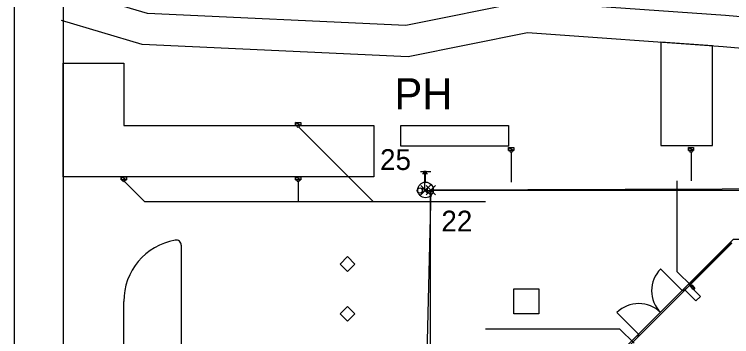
# Model space of a CAD drawing. Extents: x -263964 to -263544, y -1242317 to -1242020.
# Drawn here: x -263964.1 to -263895.1, y -1242096.7 to -1242065.7 of the extents above; entities that cross this region are included whole.
import ezdxf

# ---------------------------------------------------------------- set-up
doc = ezdxf.new("R2010")
doc.units = 0
for name, color, linetype in [('KFA_KOORDINACNA_SITUACIA_DSP_SEDA', 7, 'Continuous'), ('KFA_SO_50-2_POZIARNY_VODOVOD_BODY', 7, 'Continuous'), ('KFA_SO_50-2_POZIARNY_VODOVOD_NADZEMNE_PRVKY', 7, 'Continuous'), ('KFA_SO_50-2_POZIARNY_VODOVOD_TRASA', 7, 'Continuous'), ('POPIS', 7, 'Continuous'), ('RAM_NA_TLAC_A3_1-100', 7, 'Continuous')]:
    doc.layers.add(name, color=color, linetype=linetype)

msp = doc.modelspace()

# ---------------------------------------------------------------- linework, layer by layer
at = {"layer": 'KFA_KOORDINACNA_SITUACIA_DSP_SEDA'}
for p, q in [((-263959.468, -1242059.534), (-263959.468, -1242179.482)), ((-263896.968, -1242068.731), (-263901.968, -1242068.376)), ((-263901.968, -1242068.376), (-263901.968, -1242074.382)), ((-263896.968, -1242074.382), (-263896.968, -1242068.731)), ((-263959.468, -1242071.382), (-263959.468, -1242070.382)), ((-263959.468, -1242070.382), (-263953.617, -1242070.382)), ((-263953.617, -1242070.382), (-263953.617, -1242076.382)), ((-263959.468, -1242076.382), (-263959.468, -1242071.382)), ((-263901.968, -1242074.382), (-263901.968, -1242078.308)), ((-263896.968, -1242078.308), (-263896.968, -1242074.382)), ((-263959.468, -1242081.307), (-263959.468, -1242076.382)), ((-263953.617, -1242076.382), (-263929.58, -1242076.382)), ((-263937.093, -1242076.382), (-263937.093, -1242076.092)), ((-263937.093, -1242076.092), (-263936.593, -1242076.092)), ((-263936.593, -1242076.382), (-263937.093, -1242076.092)), ((-263936.593, -1242076.382), (-263937.093, -1242076.092)), ((-263937.093, -1242076.092), (-263937.093, -1242076.382)), ((-263936.593, -1242076.382), (-263937.093, -1242076.382)), ((-263937.093, -1242076.382), (-263936.593, -1242076.382)), ((-263936.772, -1242076.553), (-263929.628, -1242083.697)), ((-263936.593, -1242076.092), (-263936.593, -1242076.382)), ((-263929.58, -1242076.382), (-263929.58, -1242081.307)), ((-263926.968, -1242076.382), (-263921.968, -1242076.382)), ((-263926.968, -1242078.382), (-263926.968, -1242076.382)), ((-263926.968, -1242076.382), (-263926.968, -1242076.382)), ((-263921.968, -1242076.382), (-263916.593, -1242076.382)), ((-263916.593, -1242076.382), (-263916.593, -1242078.382)), ((-263921.968, -1242078.382), (-263926.968, -1242078.382)), ((-263916.593, -1242078.382), (-263921.968, -1242078.382)), ((-263916.593, -1242078.777), (-263916.593, -1242078.487)), ((-263916.593, -1242078.487), (-263916.093, -1242078.487)), ((-263916.093, -1242078.777), (-263916.593, -1242078.487)), ((-263916.093, -1242078.777), (-263916.593, -1242078.487)), ((-263916.593, -1242078.487), (-263916.593, -1242078.777)), ((-263916.093, -1242078.487), (-263916.093, -1242078.777)), ((-263901.968, -1242078.308), (-263896.968, -1242078.308)), ((-263899.296, -1242078.777), (-263899.296, -1242078.487)), ((-263899.296, -1242078.487), (-263898.796, -1242078.487)), ((-263898.796, -1242078.777), (-263899.296, -1242078.487)), ((-263898.796, -1242078.777), (-263899.296, -1242078.487)), ((-263899.296, -1242078.487), (-263899.296, -1242078.777)), ((-263898.796, -1242078.487), (-263898.796, -1242078.777)), ((-263916.093, -1242078.777), (-263916.593, -1242078.777)), ((-263916.593, -1242078.777), (-263916.093, -1242078.777)), ((-263916.343, -1242078.977), (-263916.343, -1242081.82)), ((-263898.796, -1242078.777), (-263899.296, -1242078.777)), ((-263899.296, -1242078.777), (-263898.796, -1242078.777)), ((-263899.046, -1242078.977), (-263899.047, -1242081.696)), ((-263924.768, -1242081.015), (-263924.768, -1242080.765)), ((-263924.768, -1242080.765), (-263924.518, -1242080.765)), ((-263924.518, -1242080.765), (-263924.518, -1242081.015)), ((-263953.617, -1242081.307), (-263959.468, -1242081.307)), ((-263953.868, -1242081.597), (-263953.868, -1242081.307)), ((-263953.868, -1242081.307), (-263953.368, -1242081.307)), ((-263953.368, -1242081.597), (-263953.868, -1242081.307)), ((-263953.368, -1242081.597), (-263953.868, -1242081.307)), ((-263953.868, -1242081.307), (-263953.868, -1242081.597)), ((-263929.58, -1242081.307), (-263953.617, -1242081.307)), ((-263953.368, -1242081.307), (-263953.368, -1242081.597)), ((-263937.093, -1242081.597), (-263937.093, -1242081.307)), ((-263937.093, -1242081.307), (-263936.593, -1242081.307)), ((-263936.593, -1242081.597), (-263937.093, -1242081.307)), ((-263936.593, -1242081.597), (-263937.093, -1242081.307)), ((-263937.093, -1242081.307), (-263937.093, -1242081.597)), ((-263936.593, -1242081.307), (-263936.593, -1242081.597)), ((-263924.893, -1242081.015), (-263924.768, -1242081.015)), ((-263924.643, -1242082.64), (-263924.643, -1242080.89)), ((-263924.518, -1242081.015), (-263924.393, -1242081.015)), ((-263953.368, -1242081.597), (-263953.868, -1242081.597)), ((-263953.868, -1242081.597), (-263953.368, -1242081.597)), ((-263953.618, -1242081.697), (-263951.618, -1242083.697)), ((-263953.547, -1242081.768), (-263951.618, -1242083.697)), ((-263936.593, -1242081.597), (-263937.093, -1242081.597)), ((-263937.093, -1242081.597), (-263936.593, -1242081.597)), ((-263936.843, -1242081.797), (-263936.843, -1242083.697)), ((-263900.379, -1242090.456), (-263900.379, -1242081.705)), ((-263924.393, -1242082.39), (-263924.893, -1242082.89)), ((-263924.893, -1242082.89), (-263924.893, -1242082.39)), ((-263924.893, -1242082.39), (-263924.393, -1242082.89)), ((-263924.393, -1242082.89), (-263924.393, -1242082.39)), ((-263924.393, -1242082.64), (-263924.143, -1242082.64)), ((-263788.143, -1242082.64), (-263924.143, -1242082.64)), ((-263924.143, -1242082.64), (-263924.143, -1242185.14)), ((-263951.618, -1242083.697), (-263918.806, -1242083.697)), ((-263908.663, -1242101.215), (-263895.135, -1242087.687)), ((-263895.258, -1242087.647), (-263896.566, -1242088.955)), ((-263896.548, -1242088.973), (-263895.24, -1242087.665)), ((-263895.273, -1242087.698), (-263895.245, -1242087.67)), ((-263895.202, -1242087.769), (-263895.273, -1242087.698)), ((-263895.24, -1242087.665), (-263895.258, -1242087.647)), ((-263895.245, -1242087.67), (-263895.216, -1242087.641)), ((-263895.216, -1242087.641), (-263895.146, -1242087.712)), ((-263895.146, -1242087.712), (-263895.202, -1242087.769)), ((-263948.093, -1242087.901), (-263948.093, -1242241.458)), ((-263932.8, -1242089.707), (-263932.093, -1242089)), ((-263932.093, -1242089), (-263931.386, -1242089.707)), ((-263932.093, -1242089), (-263932.093, -1242089)), ((-263897.906, -1242090.295), (-263896.598, -1242088.987)), ((-263896.58, -1242089.005), (-263897.888, -1242090.313)), ((-263896.598, -1242088.987), (-263896.58, -1242089.005)), ((-263896.592, -1242089.017), (-263896.564, -1242088.989)), ((-263896.522, -1242089.088), (-263896.592, -1242089.017)), ((-263896.566, -1242088.955), (-263896.548, -1242088.973)), ((-263896.564, -1242088.989), (-263896.536, -1242088.96)), ((-263896.536, -1242088.96), (-263896.465, -1242089.031)), ((-263896.465, -1242089.031), (-263896.522, -1242089.088)), ((-263932.093, -1242090.414), (-263932.8, -1242089.707)), ((-263931.386, -1242089.707), (-263932.093, -1242090.414)), ((-263899.866, -1242092.276), (-263901.97, -1242090.173)), ((-263899.018, -1242091.817), (-263900.379, -1242090.456)), ((-263899.25, -1242091.639), (-263897.942, -1242090.331)), ((-263897.924, -1242090.349), (-263899.232, -1242091.657)), ((-263897.942, -1242090.331), (-263897.924, -1242090.349)), ((-263897.936, -1242090.361), (-263897.908, -1242090.333)), ((-263897.865, -1242090.432), (-263897.936, -1242090.361)), ((-263897.908, -1242090.333), (-263897.88, -1242090.304)), ((-263897.888, -1242090.313), (-263897.906, -1242090.295)), ((-263897.88, -1242090.304), (-263897.809, -1242090.375)), ((-263897.809, -1242090.375), (-263897.865, -1242090.432)), ((-263899.207, -1242091.764), (-263899.631, -1242092.188)), ((-263899.255, -1242091.68), (-263899.227, -1242091.652)), ((-263899.185, -1242091.751), (-263899.255, -1242091.68)), ((-263899.232, -1242091.657), (-263899.25, -1242091.639)), ((-263899.227, -1242091.652), (-263899.199, -1242091.624)), ((-263898.147, -1242092.824), (-263899.207, -1242091.764)), ((-263899.199, -1242091.624), (-263899.128, -1242091.694)), ((-263899.128, -1242091.694), (-263899.185, -1242091.751)), ((-263898.804, -1242091.866), (-263898.882, -1242091.787)), ((-263916.093, -1242092.107), (-263913.693, -1242092.107)), ((-263916.093, -1242094.507), (-263916.093, -1242092.107)), ((-263913.693, -1242092.107), (-263913.693, -1242094.507)), ((-263899.849, -1242092.259), (-263899.866, -1242092.276)), ((-263899.764, -1242092.174), (-263899.849, -1242092.259)), ((-263899.849, -1242092.259), (-263899.764, -1242092.344)), ((-263899.679, -1242092.259), (-263899.764, -1242092.174)), ((-263899.764, -1242092.344), (-263899.679, -1242092.259)), ((-263899.631, -1242092.188), (-263898.571, -1242093.249)), ((-263898.969, -1242092.031), (-263899.047, -1242091.953)), ((-263899.047, -1242091.953), (-263898.969, -1242092.031)), ((-263898.949, -1242092.031), (-263898.969, -1242092.031)), ((-263898.861, -1242092.119), (-263898.949, -1242092.031)), ((-263898.804, -1242091.885), (-263898.804, -1242091.866)), ((-263898.715, -1242091.974), (-263898.804, -1242091.885)), ((-263898.571, -1242093.249), (-263898.147, -1242092.824)), ((-263953.617, -1242244.458), (-263953.617, -1242093.307)), ((-263932.8, -1242094.507), (-263932.093, -1242093.8)), ((-263932.093, -1242093.8), (-263931.386, -1242094.507)), ((-263932.093, -1242093.8), (-263932.093, -1242093.8)), ((-263932.093, -1242095.214), (-263932.8, -1242094.507)), ((-263931.386, -1242094.507), (-263932.093, -1242095.214)), ((-263913.693, -1242094.507), (-263916.093, -1242094.507)), ((-263904.074, -1242096.484), (-263906.177, -1242094.38)), ((-263905.894, -1242095.971), (-263918.832, -1242095.971)), ((-263904.533, -1242097.332), (-263905.894, -1242095.971)), ((-263904.176, -1242096.586), (-263904.091, -1242096.501)), ((-263904.091, -1242096.671), (-263904.176, -1242096.586)), ((-263904.091, -1242096.501), (-263904.074, -1242096.484)), ((-263904.091, -1242096.501), (-263904.006, -1242096.586)), ((-263904.006, -1242096.586), (-263904.091, -1242096.671))]:
    msp.add_line(p, q, dxfattribs=at)
for points in [[(-263864.257, -1242068.593), (-263895.733, -1242065.811), (-263914.971, -1242064.445), (-263926.501, -1242066.77), (-263951.337, -1242065.625), (-263959.611, -1242063.145)], [(-263864.521, -1242071.581), (-263895.971, -1242068.802), (-263914.777, -1242067.467), (-263926.271, -1242069.784), (-263951.845, -1242068.605), (-263959.611, -1242066.277)], [(-263794.893, -1242227.382), (-263808.968, -1242241.457), (-263894.968, -1242241.457), (-263909.043, -1242227.382), (-263909.043, -1242196.333), (-263914.143, -1242196.333), (-263914.143, -1242132.433), (-263909.043, -1242132.433), (-263909.043, -1242101.382), (-263894.968, -1242087.307), (-263808.968, -1242087.307), (-263794.893, -1242101.382), (-263794.893, -1242227.382)]]:
    msp.add_lwpolyline(points, dxfattribs=at)
for centre, radius in [((-263936.843, -1242076.482), 0.1), ((-263916.343, -1242078.877), 0.1), ((-263899.046, -1242078.877), 0.1), ((-263953.618, -1242081.697), 0.1), ((-263936.843, -1242081.697), 0.1), ((-263925.143, -1242082.64), 0.25), ((-263898.965, -1242091.87), 0.075), ((-263898.788, -1242092.047), 0.075)]:
    msp.add_circle(centre, radius, dxfattribs=at)
for centre, radius, start, end in [((-263947.634, -1242093.3), 5.983, 100.0694, 180.06602), ((-263948.593, -1242087.901), 0.5, 0, 100.0694), ((-263899.866, -1242092.276), 2.975, 135.00007, 225.00006), ((-263898.965, -1242091.87), 0.117, 45, 225), ((-263898.788, -1242092.047), 0.103, 225, 45), ((-263904.074, -1242096.484), 2.975, 44.99994, 134.99992)]:
    msp.add_arc(centre, radius, start, end, dxfattribs=at)
at = {"layer": 'KFA_SO_50-2_POZIARNY_VODOVOD_BODY'}
for p, q in [((-263925.033, -1242083.027), (-263924.149, -1242082.143)), ((-263924.149, -1242083.027), (-263925.033, -1242082.143)), ((-263924.522, -1242083.055), (-263923.638, -1242082.171)), ((-263923.638, -1242083.055), (-263924.522, -1242082.171)), ((-263924.591, -1242082.585), (-263924.591, -1242082.585)), ((-263924.08, -1242082.613), (-263924.08, -1242082.613))]:
    msp.add_line(p, q, dxfattribs=at)
at = {"layer": 'KFA_SO_50-2_POZIARNY_VODOVOD_NADZEMNE_PRVKY'}
for points in [[(-263924.091, -1242080.835), (-263925.091, -1242080.835)], [(-263924.591, -1242081.835), (-263924.591, -1242080.835)], [(-263924.061, -1242082.055), (-263925.121, -1242083.115)]]:
    msp.add_lwpolyline(points, dxfattribs=at)
msp.add_circle((-263924.591, -1242082.585), 0.75, dxfattribs=at)
at = {"layer": 'KFA_SO_50-2_POZIARNY_VODOVOD_TRASA'}
msp.add_lwpolyline([(-263924.931, -1242185.127), (-263924.146, -1242197.091), (-263924.296, -1242220.899), (-263924.1, -1242250.121), (-263913.986, -1242249.798), (-263886.91, -1242249.876), (-263867.714, -1242249.83), (-263837.257, -1242249.836), (-263828.162, -1242249.901), (-263787.99, -1242250.032), (-263788.202, -1242220.837), (-263788.195, -1242200.509), (-263788.092, -1242179.915), (-263788.062, -1242148.958), (-263787.919, -1242127.952), (-263787.952, -1242110.966), (-263788.129, -1242082.536), (-263828.429, -1242082.723), (-263836.783, -1242082.559), (-263867.306, -1242082.615), (-263886.71, -1242082.472), (-263924.08, -1242082.613), (-263924.644, -1242106.322), (-263924.479, -1242117.427)], close=True, dxfattribs=at)
at = {"layer": 'RAM_NA_TLAC_A3_1-100'}
msp.add_lwpolyline([(-263964.149, -1242020.359), (-263544.149, -1242020.359), (-263544.149, -1242317.359), (-263964.149, -1242317.359)], close=True, dxfattribs=at)

# ---------------------------------------------------------------- texts
at = {"layer": 'KFA_SO_50-2_POZIARNY_VODOVOD_BODY'}
for s, p in [('25', (-263928.964, -1242080.662)), ('22', (-263923.064, -1242086.578))]:
    msp.add_text(s, height=2, dxfattribs=at).set_placement(p)
at = {"layer": 'POPIS'}
msp.add_text('PH', height=3, dxfattribs=at).set_placement((-263927.582, -1242074.841))

doc.saveas('drawing.dxf')
